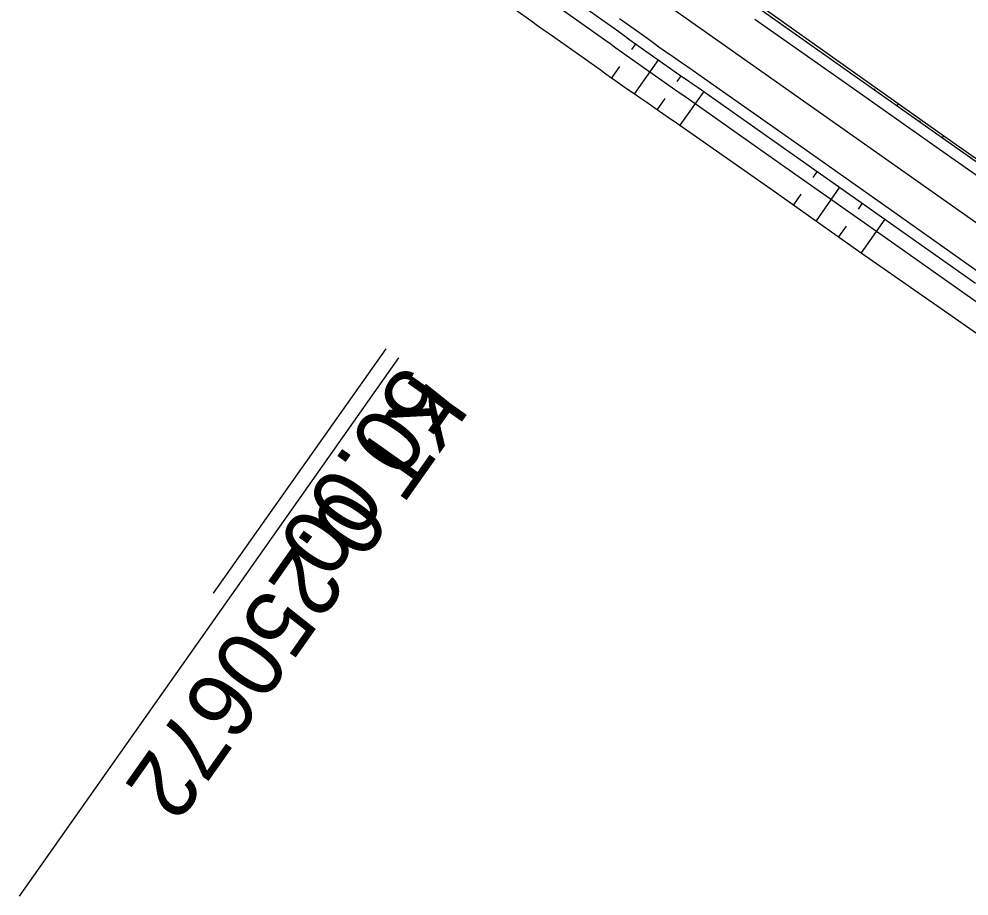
# Model space of a CAD drawing. Extents: x -481656 to -478728, y -1113199 to -1110710.
# Drawn here: x -480796.28 to -480753.43, y -1112781.89 to -1112742.33 of the extents above; entities that cross this region are included whole.
import ezdxf

# ---------------------------------------------------------------- set-up
doc = ezdxf.new("R2010")
doc.units = 0
for name, color, linetype in [('C13_HATCH_SLOPE_L', 7, 'Continuous'), ('C13_HATCH_SLOPE_R', 7, 'Continuous'), ('C13_HLBODY', 7, 'Continuous'), ('C13_HRANA_TELESO', 7, 'Continuous'), ('C13_KORUNA', 7, 'Continuous'), ('C13_OSA', 7, 'Continuous'), ('C13_PRIKOP', 7, 'Continuous'), ('C13_STANICENI', 7, 'Continuous'), ('C13_VOZOVKA', 7, 'Continuous'), ('C13_ZPEVKRAJ', 7, 'Continuous')]:
    doc.layers.add(name, color=color, linetype=linetype)

msp = doc.modelspace()

# ---------------------------------------------------------------- linework, layer by layer
at = {"layer": 'C13_HATCH_SLOPE_L'}
for p, q in [((-480757.695, -1112745.527), (-480757.662, -1112745.48)), ((-480757.629, -1112745.433), (-480757.629, -1112745.433)), ((-480756.673, -1112746.248), (-480756.608, -1112746.155)), ((-480755.652, -1112746.968), (-480755.62, -1112746.922)), ((-480755.587, -1112746.876), (-480755.587, -1112746.876)), ((-480754.63, -1112747.688), (-480754.566, -1112747.598))]:
    msp.add_line(p, q, dxfattribs=at)
at = {"layer": 'C13_HATCH_SLOPE_R'}
for p, q in [((-480768.461, -1112743.443), (-480768.653, -1112743.716)), ((-480769.194, -1112744.482), (-480769.542, -1112744.977)), ((-480767.439, -1112744.163), (-480768.518, -1112745.693)), ((-480766.418, -1112744.883), (-480766.61, -1112745.156)), ((-480765.396, -1112745.604), (-480766.47, -1112747.127)), ((-480767.148, -1112745.919), (-480767.494, -1112746.41)), ((-480760.288, -1112749.205), (-480760.48, -1112749.478)), ((-480759.266, -1112749.925), (-480760.333, -1112751.438)), ((-480761.013, -1112750.234), (-480761.354, -1112750.717)), ((-480758.245, -1112750.646), (-480758.437, -1112750.918)), ((-480757.223, -1112751.366), (-480758.292, -1112752.882)), ((-480758.971, -1112751.675), (-480759.313, -1112752.16))]:
    msp.add_line(p, q, dxfattribs=at)
at = {"layer": 'C13_HLBODY'}
msp.add_line((-480779.161, -1112757.617), (-480796.275, -1112781.89), dxfattribs=at)
at = {"layer": 'C13_HRANA_TELESO'}
for p, q in [((-480762.731, -1112741.823), (-480758.649, -1112744.712)), ((-480758.649, -1112744.712), (-480754.566, -1112747.598)), ((-480766.47, -1112747.127), (-480762.374, -1112749.995)), ((-480754.566, -1112747.598), (-480750.485, -1112750.486)), ((-480762.374, -1112749.995), (-480758.292, -1112752.882)), ((-480758.292, -1112752.882), (-480754.188, -1112755.739)), ((-480754.188, -1112755.739), (-480750.091, -1112758.604))]:
    msp.add_line(p, q, dxfattribs=at)
for centre, radius, start, end in [((-480480.966, -1112331.599), 504.14, 234.36572, 234.93868), ((-480624.003, -1112539.183), 252.066, 234.44634, 235.58416)]:
    msp.add_arc(centre, radius, start, end, dxfattribs=at)
at = {"layer": 'C13_KORUNA'}
for p, q in [((-480762.803, -1112741.926), (-480758.717, -1112744.807)), ((-480758.717, -1112744.807), (-480754.63, -1112747.688)), ((-480765.396, -1112745.604), (-480761.31, -1112748.485)), ((-480754.63, -1112747.688), (-480750.544, -1112750.569)), ((-480761.31, -1112748.485), (-480757.223, -1112751.366)), ((-480757.223, -1112751.366), (-480753.137, -1112754.247))]:
    msp.add_line(p, q, dxfattribs=at)
for centre, radius, start, end in [((-480479.523, -1112332.626), 502.25, 234.16444, 234.7374), ((-480622.724, -1112538.944), 251.125, 234.23839, 235.37989)]:
    msp.add_arc(centre, radius, start, end, dxfattribs=at)
at = {"layer": 'C13_OSA'}
msp.add_line((-480767.637, -1112741.271), (-480724.708, -1112771.538), dxfattribs=at)
at = {"layer": 'C13_PRIKOP'}
for p, q in [((-480765.78, -1112746.148), (-480761.694, -1112749.03)), ((-480761.694, -1112749.03), (-480757.607, -1112751.911)), ((-480757.607, -1112751.911), (-480753.521, -1112754.792)), ((-480753.521, -1112754.792), (-480749.434, -1112757.673))]:
    msp.add_line(p, q, dxfattribs=at)
for centre, radius, start, end in [((-480479.523, -1112332.626), 502.916, 234.16444, 234.7374), ((-480622.916, -1112539.216), 251.458, 234.23904, 235.37923)]:
    msp.add_arc(centre, radius, start, end, dxfattribs=at)
at = {"layer": 'C13_STANICENI'}
msp.add_line((-480779.732, -1112757.214), (-480787.526, -1112768.237), dxfattribs=at)
at = {"layer": 'C13_VOZOVKA'}
for p, q in [((-480763.091, -1112742.335), (-480759.005, -1112745.216)), ((-480765.108, -1112745.195), (-480761.021, -1112748.076)), ((-480759.005, -1112745.216), (-480754.918, -1112748.097)), ((-480761.021, -1112748.076), (-480756.935, -1112750.957)), ((-480754.918, -1112748.097), (-480750.832, -1112750.978)), ((-480756.935, -1112750.957), (-480752.849, -1112753.838))]:
    msp.add_line(p, q, dxfattribs=at)
msp.add_arc((-480622.579, -1112538.739), 250.875, 234.23791, 235.38038, dxfattribs=at)
at = {"layer": 'C13_ZPEVKRAJ'}
for p, q in [((-480763.091, -1112742.335), (-480759.005, -1112745.216)), ((-480765.108, -1112745.195), (-480761.021, -1112748.076)), ((-480759.005, -1112745.216), (-480754.918, -1112748.097)), ((-480761.021, -1112748.076), (-480756.935, -1112750.957)), ((-480754.918, -1112748.097), (-480750.832, -1112750.978)), ((-480756.935, -1112750.957), (-480752.849, -1112753.838))]:
    msp.add_line(p, q, dxfattribs=at)
msp.add_arc((-480622.579, -1112538.739), 250.875, 234.23791, 235.38038, dxfattribs=at)

# ---------------------------------------------------------------- texts
at = {"layer": 'C13_HLBODY'}
msp.add_text('KT 0.250672', height=2.999, rotation=234.8144, dxfattribs=at).set_placement((-480778.344, -1112758.192))
at = {"layer": 'C13_STANICENI'}
msp.add_text('50.00', height=2.999, rotation=234.7374, dxfattribs=at).set_placement((-480778.915, -1112757.79))

doc.saveas('drawing.dxf')
